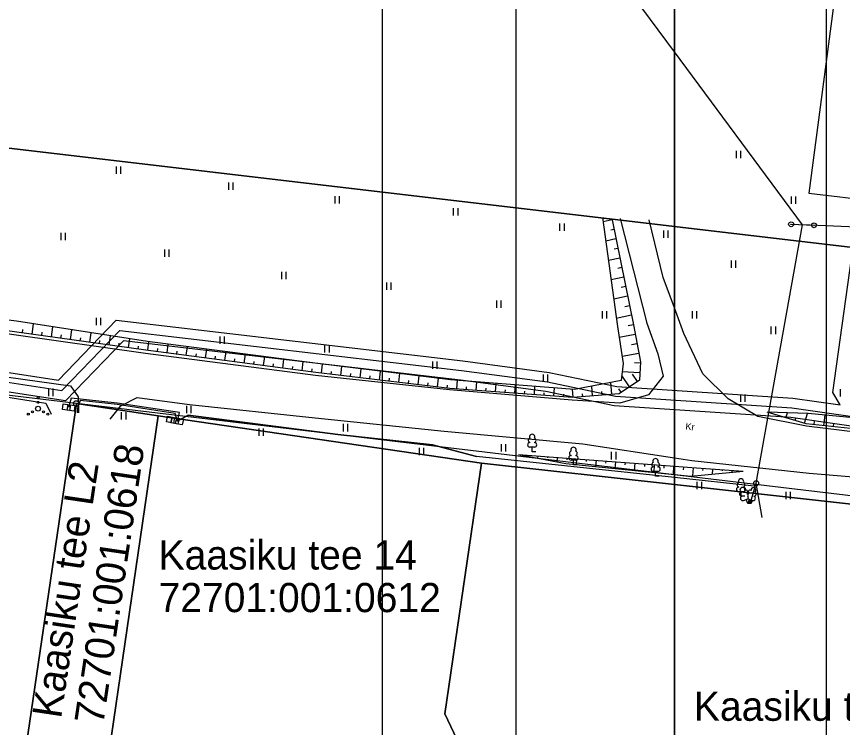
# Model space of a CAD drawing. Extents: x 532656 to 533339, y 6581345 to 6581629.
# Drawn here: x 532930.1 to 533015, y 6581458.9 to 6581531.9 of the extents above; entities that cross this region are included whole.
import ezdxf

# ---------------------------------------------------------------- set-up
doc = ezdxf.new("R2010")
doc.units = 0
for name, color, linetype in [('ELRAJATISMP', 7, 'Continuous'), ('HALJASTUS', 7, 'Continuous'), ('KASUTUSALA', 7, 'Continuous'), ('MPKAABEL', 7, 'Continuous'), ('MPOHULIIN', 7, 'Continuous'), ('PIIR', 7, 'Continuous'), ('PIIRIMLEITUD', 7, 'Continuous'), ('POST', 7, 'Continuous'), ('PR_SIDE', 7, 'Continuous'), ('PUU', 7, 'Continuous'), ('RAJATIS', 7, 'Continuous'), ('RELJEEF', 7, 'Continuous'), ('TEE', 7, 'Continuous'), ('VORMISTUS', 7, 'Continuous'), ('VORMISTUS_1', 7, 'Continuous')]:
    doc.layers.add(name, color=color, linetype=linetype)

msp = doc.modelspace()

# ---------------------------------------------------------------- linework, layer by layer
at = {"layer": 'ELRAJATISMP'}
for p, q in [((532935.363, 6581492.081), (532935.278, 6581491.49)), ((532935.632, 6581492.042), (532935.546, 6581491.452)), ((532946.08, 6581490.776), (532945.961, 6581490.191)), ((532946.346, 6581490.722), (532946.227, 6581490.137)), ((532946.53, 6581490.696), (532946.415, 6581490.11)), ((532946.797, 6581490.643), (532946.681, 6581490.058))]:
    msp.add_line(p, q, dxfattribs=at)
for points in [[(532934.906, 6581492.147), (532936.088, 6581491.977), (532936.003, 6581491.386), (532934.821, 6581491.556)], [(532945.627, 6581490.868), (532946.798, 6581490.63), (532946.679, 6581490.046), (532945.509, 6581490.283)], [(532946.077, 6581490.785), (532947.249, 6581490.554), (532947.134, 6581489.969), (532945.962, 6581490.199)]]:
    msp.add_lwpolyline(points, close=True, dxfattribs=at)
at = {"layer": 'HALJASTUS'}
for p, q in [((533004.032, 6581518.145), (533004.032, 6581517.384)), ((533004.487, 6581518.145), (533004.487, 6581517.384)), ((532940.342, 6581516.519), (532940.342, 6581515.758)), ((532940.797, 6581516.519), (532940.797, 6581515.758)), ((532951.862, 6581514.893), (532951.862, 6581514.132)), ((532952.317, 6581514.893), (532952.317, 6581514.132)), ((532962.792, 6581513.489), (532962.792, 6581512.728)), ((532963.247, 6581513.489), (532963.247, 6581512.728)), ((533009.686, 6581513.457), (533009.686, 6581512.696)), ((533010.141, 6581513.457), (533010.141, 6581512.696)), ((532974.977, 6581512.233), (532974.977, 6581511.472)), ((532975.432, 6581512.233), (532975.432, 6581511.472)), ((532985.907, 6581510.681), (532985.907, 6581509.92)), ((532986.362, 6581510.681), (532986.362, 6581509.92)), ((532934.652, 6581509.708), (532934.652, 6581508.947)), ((532935.107, 6581509.708), (532935.107, 6581508.947)), ((532996.562, 6581509.952), (532996.562, 6581509.191)), ((532997.017, 6581509.952), (532997.017, 6581509.191)), ((532945.287, 6581508.008), (532945.287, 6581507.247)), ((532945.742, 6581508.008), (532945.742, 6581507.247)), ((533003.525, 6581506.87), (533003.525, 6581506.109)), ((533003.98, 6581506.87), (533003.98, 6581506.109)), ((532957.324, 6581505.717), (532957.324, 6581504.956)), ((532957.779, 6581505.717), (532957.779, 6581504.956)), ((532968.106, 6581504.609), (532968.106, 6581503.848)), ((532968.561, 6581504.609), (532968.561, 6581503.848)), ((532979.405, 6581502.761), (532979.405, 6581502)), ((532979.86, 6581502.761), (532979.86, 6581502)), ((532990.261, 6581501.653), (532990.261, 6581500.892)), ((532990.716, 6581501.653), (532990.716, 6581500.892)), ((532999.516, 6581501.676), (532999.516, 6581500.914)), ((532999.971, 6581501.676), (532999.971, 6581500.914)), ((532938.271, 6581500.988), (532938.271, 6581500.227)), ((532938.726, 6581500.988), (532938.726, 6581500.227)), ((533007.618, 6581500.071), (533007.618, 6581499.31)), ((533008.074, 6581500.071), (533008.074, 6581499.31)), ((532950.973, 6581499.067), (532950.973, 6581498.305)), ((532951.428, 6581499.067), (532951.428, 6581498.305)), ((532961.755, 6581498.18), (532961.755, 6581497.419)), ((532962.21, 6581498.18), (532962.21, 6581497.419)), ((532972.832, 6581496.48), (532972.832, 6581495.719)), ((532973.287, 6581496.48), (532973.287, 6581495.719)), ((532984.205, 6581495.15), (532984.205, 6581494.389)), ((532984.66, 6581495.15), (532984.66, 6581494.389)), ((532933.385, 6581493.7), (532933.385, 6581492.939)), ((532933.84, 6581493.7), (532933.84, 6581492.939)), ((533014.75, 6581493.652), (533014.75, 6581492.891)), ((533004.496, 6581493.103), (533004.496, 6581492.342)), ((533004.951, 6581493.103), (533004.951, 6581492.342)), ((532947.564, 6581491.926), (532947.564, 6581491.165)), ((532948.019, 6581491.926), (532948.019, 6581491.165)), ((532940.86, 6581491.299), (532940.86, 6581490.538)), ((532941.315, 6581491.299), (532941.315, 6581490.538)), ((532954.997, 6581489.604), (532954.997, 6581488.842)), ((532955.452, 6581489.604), (532955.452, 6581488.842)), ((532963.648, 6581490.068), (532963.648, 6581489.307)), ((532964.103, 6581490.068), (532964.103, 6581489.307)), ((532979.901, 6581487.993), (532979.901, 6581487.232)), ((532980.356, 6581487.993), (532980.356, 6581487.232)), ((532971.455, 6581487.619), (532971.455, 6581486.858)), ((532971.91, 6581487.619), (532971.91, 6581486.858)), ((532991.21, 6581487.191), (532991.21, 6581486.429)), ((532991.665, 6581487.191), (532991.665, 6581486.429)), ((533000.018, 6581484.132), (533000.018, 6581483.371)), ((533000.473, 6581484.132), (533000.473, 6581483.371)), ((533009.133, 6581483.1), (533009.133, 6581482.339)), ((533009.588, 6581483.1), (533009.588, 6581482.339))]:
    msp.add_line(p, q, dxfattribs=at)
msp.add_lwpolyline([(532892.02, 6581496.19), (532895.502, 6581498.379), (532904.073, 6581497.349), (532916.051, 6581494.964), (532928.105, 6581493.009), (532933.125, 6581492.214), (532933.659, 6581491.084)], dxfattribs=at)
for centre, radius in [((532932.31, 6581492.791), 0.1), ((532932.31, 6581491.641), 0.25), ((532932.31, 6581492.291), 0.1), ((532931.31, 6581491.066), 0.1), ((532931.745, 6581491.316), 0.1), ((532932.875, 6581491.316), 0.1), ((532933.31, 6581491.066), 0.1)]:
    msp.add_circle(centre, radius, dxfattribs=at)
at = {"layer": 'KASUTUSALA'}
for points in [[(532799.662, 6581479.424), (532838.202, 6581500.971), (532843.839, 6581502.808), (532856.06, 6581504.74), (532864.381, 6581504.708), (532878.783, 6581502.228), (532905.462, 6581499.009), (532934.405, 6581494.582), (532940.328, 6581500.726), (532975.953, 6581496.54), (532984.828, 6581495.375), (532991.779, 6581493.915), (533009.862, 6581492.726), (533014.729, 6581492.033), (533013.98, 6581493.304), (533015.896, 6581507.087)], [(533020.132, 6581489.243), (533009.655, 6581490.735), (532991.507, 6581491.928), (532984.492, 6581493.402), (532975.706, 6581494.555), (532941.079, 6581498.624), (532935.126, 6581492.449), (532905.191, 6581497.027), (532878.493, 6581500.248), (532864.206, 6581502.709), (532856.214, 6581502.739), (532844.308, 6581500.857), (532839.008, 6581499.129), (532800.682, 6581477.703)]]:
    msp.add_lwpolyline(points, dxfattribs=at)
at = {"layer": 'MPKAABEL'}
for p, q in [((532997.696, 6581484.555), (532977.35, 6581486.727)), ((533005.909, 6581483.678), (532997.696, 6581484.555))]:
    msp.add_line(p, q, dxfattribs=at)
for points in [[(532946.644, 6581490.354), (532946.827, 6581491.247), (532940.446, 6581492.21), (532935.695, 6581492.724), (532935.431, 6581491.762)], [(532946.644, 6581490.354), (532946.827, 6581491.247), (532940.446, 6581492.21), (532935.695, 6581492.724), (532935.431, 6581491.762)], [(532946.644, 6581490.354), (532946.385, 6581491.162), (532940.427, 6581492.061), (532936.642, 6581492.471), (532936.375, 6581491.643), (532936.311, 6581491.217)], [(532946.644, 6581490.354), (532946.385, 6581491.162), (532940.427, 6581492.061), (532936.642, 6581492.471), (532936.375, 6581491.643), (532936.311, 6581491.217)], [(532997.696, 6581484.555), (532977.35, 6581486.727), (532972.847, 6581487.936), (532963.128, 6581488.985), (532947.726, 6581490.986), (532946.644, 6581490.354)], [(532946.644, 6581490.354), (532947.726, 6581490.986), (532963.128, 6581488.985), (532972.847, 6581487.936), (532977.35, 6581486.727)], [(533006.107, 6581483.987), (533005.909, 6581483.678), (532997.696, 6581484.555)]]:
    msp.add_lwpolyline(points, dxfattribs=at)
at = {"layer": 'MPOHULIIN'}
msp.add_line((532997.696, 6581528.314), (532981.493, 6581550.179), dxfattribs=at)
for points in [[(533275.324, 6581502.368), (533268.528, 6581499.278), (533228.294, 6581500.866), (533187.877, 6581502.842), (533141.428, 6581504.881), (533095.447, 6581506.847), (533050.545, 6581508.805), (533010.87, 6581510.537), (532997.696, 6581528.314)], [(533006.722, 6581480.474), (533006.107, 6581483.987), (533010.87, 6581510.537)]]:
    msp.add_lwpolyline(points, dxfattribs=at)
at = {"layer": 'PIIR'}
for points in [[(532997.696, 6581510.35), (532853.02, 6581527.38), (532766.54, 6581476.67), (532710.965, 6581584.147)], [(532997.696, 6581558.346), (533016.96, 6581555.16), (533011.51, 6581513.79), (533060.19, 6581508.02), (533066.33, 6581546.98), (533091.13, 6581542.87), (533143.65, 6581562.67), (533173.8, 6581529.09), (533205.25, 6581513.98), (533125.12, 6581495.35), (532997.696, 6581510.35)], [(532997.696, 6581510.35), (533125.12, 6581495.35), (533271.76, 6581529.44), (533289.68, 6581507.68), (533127.07, 6581468.59), (533126.77, 6581469.47), (532997.696, 6581484.842)], [(532997.696, 6581484.842), (532936.25, 6581492.16), (532895.36, 6581497.07), (532858.61, 6581500.62), (532765.26, 6581446.64), (532740.99, 6581450.83), (532726.7, 6581453.3), (532853.02, 6581527.38), (532997.696, 6581510.35)], [(532997.696, 6581484.842), (532936.25, 6581492.16), (532944.64, 6581490.92), (532977.88, 6581486.06), (532997.696, 6581483.863)], [(532997.696, 6581483.863), (532977.88, 6581486.06), (532974.12, 6581460.29), (532983.42, 6581440.62), (532985.67, 6581435.87), (532997.696, 6581433.84)], [(532997.696, 6581483.863), (533035.33, 6581479.69), (533123.26, 6581468.15), (533127.07, 6581468.59), (533126.77, 6581469.47), (532997.696, 6581484.842)], [(532997.696, 6581433.84), (533019.26, 6581430.2), (533032.98, 6581458.23), (533035.33, 6581479.69), (532997.696, 6581483.863)]]:
    msp.add_lwpolyline(points, dxfattribs=at)
for points in [[(533066.33, 6581546.98), (533016.96, 6581555.16), (533011.51, 6581513.79), (533060.19, 6581508.02)], [(532895.36, 6581497.07), (532888.42, 6581457.95), (532930.2, 6581450.9), (532936.25, 6581492.16)], [(532936.25, 6581492.16), (532930.2, 6581450.9), (532937.97, 6581439.75), (532947.82, 6581446.61), (532939.84, 6581458.06), (532944.64, 6581490.92)], [(532944.64, 6581490.92), (532939.84, 6581458.06), (532947.82, 6581446.61), (532983.42, 6581440.62), (532974.12, 6581460.29), (532977.88, 6581486.06)]]:
    msp.add_lwpolyline(points, close=True, dxfattribs=at)
at = {"layer": 'PIIRIMLEITUD'}
msp.add_circle((532936.233, 6581492.169), 0.285, dxfattribs=at)
at = {"layer": 'POST'}
msp.add_lwpolyline([(533005.546, 6581482.101), (533006.107, 6581483.987)], dxfattribs=at)
for centre, radius in [((533009.691, 6581510.589), 0.25), ((533009.691, 6581510.589), 0.0234), ((533012.048, 6581510.486), 0.25), ((533012.048, 6581510.486), 0.0234), ((533006.107, 6581483.987), 0.25), ((533005.546, 6581482.101), 0.125), ((533005.546, 6581482.101), 0.105), ((533005.546, 6581482.101), 0.0851), ((533005.546, 6581482.101), 0.0651), ((533005.546, 6581482.101), 0.0451), ((533005.546, 6581482.101), 0.0251), ((533005.546, 6581482.101), 0.00511)]:
    msp.add_circle(centre, radius, dxfattribs=at)
at = {"layer": 'PR_SIDE'}
msp.add_lwpolyline([(532685.797, 6581460.812), (532752.673, 6581449.895), (532752.642, 6581449.863), (532756.241, 6581452.319), (532771.22, 6581460.368), (532800.172, 6581478.564), (532838.605, 6581500.05), (532844.074, 6581501.833), (532856.137, 6581503.74), (532864.294, 6581503.709), (532878.638, 6581501.239), (532905.327, 6581498.018), (532934.766, 6581493.516), (532940.704, 6581499.675), (532975.83, 6581495.548), (532984.66, 6581494.389), (532991.644, 6581492.922), (533009.759, 6581491.731), (533020.322, 6581490.227)], dxfattribs=at)
at = {"layer": 'PUU'}
for p, q in [((532983.32, 6581487.693), (532982.84, 6581487.693)), ((532983.08, 6581487.218), (532983.08, 6581487.693)), ((532983.46, 6581487.218), (532983.08, 6581487.218)), ((532987.559, 6581486.356), (532987.079, 6581486.356)), ((532987.319, 6581485.881), (532987.319, 6581486.356)), ((532987.699, 6581485.881), (532987.319, 6581485.881)), ((532996.01, 6581485.187), (532995.53, 6581485.187)), ((532995.77, 6581484.712), (532995.77, 6581485.187)), ((532996.15, 6581484.712), (532995.77, 6581484.712)), ((533004.785, 6581483.113), (533004.306, 6581483.113)), ((533004.545, 6581482.638), (533004.545, 6581483.113)), ((533004.926, 6581482.638), (533004.545, 6581482.638)), ((533004.81, 6581482.218), (533005.255, 6581482.393)), ((533005.25, 6581481.883), (533005.075, 6581482.323)), ((533005.25, 6581481.883), (533005.43, 6581482.323)), ((533005.63, 6581481.883), (533005.25, 6581481.883)), ((533005.255, 6581482.393), (533005.695, 6581482.213))]:
    msp.add_line(p, q, dxfattribs=at)
msp.add_lwpolyline([(533005.255, 6581482.888), (533005.235, 6581482.813), (533005.235, 6581482.793), (533005.245, 6581482.763), (533005.265, 6581482.728), (533005.27, 6581482.708), (533005.255, 6581482.673), (533005.23, 6581482.623), (533005.225, 6581482.598), (533005.23, 6581482.583), (533005.24, 6581482.553), (533005.275, 6581482.493), (533005.28, 6581482.473), (533005.275, 6581482.453), (533005.26, 6581482.418), (533005.255, 6581482.393)], dxfattribs=at)
for centre, radius, start, end in [((532982.91, 6581488.39), 0.233, 109.02174, 253.14154), ((532983.08, 6581488.738), 0.277, 332.5799, 207.4201), ((532983.25, 6581488.39), 0.233, 286.85082, 70.98591), ((532982.842, 6581487.93), 0.238, 90.0016, 269.3953), ((532983.317, 6581487.93), 0.238, 270.6047, 89.9984), ((532987.319, 6581487.401), 0.277, 332.5799, 207.4201), ((532987.081, 6581486.594), 0.238, 90.0016, 269.3953), ((532987.148, 6581487.054), 0.233, 109.02174, 253.14154), ((532987.489, 6581487.054), 0.233, 286.85082, 70.98591), ((532987.556, 6581486.594), 0.238, 270.6047, 89.9984), ((532995.6, 6581485.884), 0.233, 109.02174, 253.14154), ((532995.77, 6581486.232), 0.277, 332.5799, 207.4201), ((532995.94, 6581485.884), 0.233, 286.85082, 70.98591), ((532995.533, 6581485.424), 0.238, 90.0016, 269.3953), ((532996.008, 6581485.424), 0.238, 270.6047, 89.9984), ((533004.545, 6581484.158), 0.277, 332.5799, 207.4201), ((533004.308, 6581483.351), 0.238, 90.0016, 269.3953), ((533004.375, 6581483.811), 0.233, 109.02174, 253.14154), ((533004.693, 6581483.297), 0.256, 111.50269, 232.51731), ((533004.693, 6581483.297), 0.256, 350.48556, 111.50017), ((533004.716, 6581483.811), 0.233, 286.85082, 70.98591), ((533004.783, 6581483.351), 0.238, 270.6047, 89.9984), ((533005.829, 6581483.289), 0.256, 67.6168, 188.63142), ((533005.829, 6581483.289), 0.256, 306.59966, 67.61428), ((533004.619, 6581482.886), 0.224, 111.43041, 274.49868), ((533004.724, 6581482.442), 0.237, 111.50143, 291.50036), ((533005.028, 6581483.047), 0.224, 308.50412, 111.57247), ((533005.254, 6581482.65), 0.237, 66.76552, 111.50149), ((533005.491, 6581483.042), 0.225, 67.7016, 230.51262), ((533005.785, 6581482.433), 0.237, 247.61661, 67.61554), ((533005.897, 6581482.876), 0.224, 264.6183, 67.68657)]:
    msp.add_arc(centre, radius, start, end, dxfattribs=at)
at = {"layer": 'RAJATIS'}
msp.add_line((533009.691, 6581510.589), (533012.048, 6581510.486), dxfattribs=at)
at = {"layer": 'RELJEEF'}
for p, q in [((532991.295, 6581511.036), (532990.379, 6581510.849)), ((532991.494, 6581510.056), (532991.167, 6581509.989)), ((532991.694, 6581509.076), (532990.649, 6581508.863)), ((532991.894, 6581508.096), (532991.524, 6581508.021)), ((532992.093, 6581507.116), (532990.919, 6581506.877)), ((532992.293, 6581506.136), (532991.88, 6581506.052)), ((532992.493, 6581505.157), (532991.189, 6581504.891)), ((532992.692, 6581504.177), (532992.236, 6581504.084)), ((532992.892, 6581503.197), (532991.46, 6581502.905)), ((532993.092, 6581502.217), (532992.593, 6581502.115)), ((532993.291, 6581501.237), (532991.73, 6581500.919)), ((532930.704, 6581499.429), (532930.754, 6581499.789)), ((532931.694, 6581499.291), (532931.842, 6581500.356)), ((532933.675, 6581499.016), (532933.819, 6581500.051)), ((532935.656, 6581498.741), (532935.796, 6581499.746)), ((532993.491, 6581500.257), (532992.95, 6581500.147)), ((532932.685, 6581499.153), (532932.733, 6581499.504)), ((532934.666, 6581498.878), (532934.713, 6581499.218)), ((532936.647, 6581498.603), (532936.692, 6581498.933)), ((532937.637, 6581498.465), (532937.772, 6581499.44)), ((532939.618, 6581498.19), (532939.749, 6581499.135)), ((532941.599, 6581497.915), (532941.726, 6581498.83)), ((532993.675, 6581499.274), (532992.018, 6581498.964)), ((532938.628, 6581498.328), (532938.672, 6581498.648)), ((532940.608, 6581498.053), (532940.652, 6581498.363)), ((532942.589, 6581497.777), (532942.631, 6581498.077)), ((532943.58, 6581497.641), (532943.698, 6581498.529)), ((532945.563, 6581497.378), (532945.681, 6581498.272)), ((532947.545, 6581497.116), (532947.665, 6581498.015)), ((532993.86, 6581498.292), (532993.297, 6581498.186)), ((532944.571, 6581497.51), (532944.611, 6581497.807)), ((532946.554, 6581497.247), (532946.594, 6581497.546)), ((532948.537, 6581496.984), (532948.577, 6581497.285)), ((532949.528, 6581496.853), (532949.648, 6581497.757)), ((532950.519, 6581496.722), (532950.56, 6581497.024)), ((532951.511, 6581496.59), (532951.631, 6581497.5)), ((532953.493, 6581496.327), (532953.615, 6581497.243)), ((532955.476, 6581496.065), (532955.598, 6581496.986)), ((532994.044, 6581497.309), (532992.326, 6581496.986)), ((532952.502, 6581496.459), (532952.542, 6581496.763)), ((532954.485, 6581496.196), (532954.525, 6581496.502)), ((532956.467, 6581495.933), (532956.508, 6581496.242)), ((532957.459, 6581495.802), (532957.582, 6581496.729)), ((532959.441, 6581495.539), (532959.565, 6581496.472)), ((532961.425, 6581495.285), (532961.535, 6581496.22)), ((532994.198, 6581496.324), (532993.603, 6581496.356)), ((532958.45, 6581495.671), (532958.491, 6581495.981)), ((532960.433, 6581495.408), (532960.474, 6581495.72)), ((532962.418, 6581495.168), (532962.455, 6581495.478)), ((532963.411, 6581495.051), (532963.521, 6581495.978)), ((532965.398, 6581494.816), (532965.506, 6581495.735)), ((532967.384, 6581494.582), (532967.491, 6581495.492)), ((532994.143, 6581495.325), (532992.338, 6581495.423)), ((532964.405, 6581494.933), (532964.441, 6581495.241)), ((532966.391, 6581494.699), (532966.427, 6581495.004)), ((532968.377, 6581494.465), (532968.413, 6581494.767)), ((532969.37, 6581494.348), (532969.476, 6581495.249)), ((532970.363, 6581494.231), (532970.398, 6581494.53)), ((532971.356, 6581494.114), (532971.462, 6581495.006)), ((532973.343, 6581493.88), (532973.447, 6581494.763)), ((532975.332, 6581493.676), (532975.398, 6581494.555)), ((532993.069, 6581493.88), (532992.296, 6581495.039)), ((532993.901, 6581494.434), (532993.389, 6581495.203)), ((532972.35, 6581493.997), (532972.384, 6581494.293)), ((532974.336, 6581493.763), (532974.37, 6581494.056)), ((532976.329, 6581493.601), (532976.351, 6581493.893)), ((532977.326, 6581493.526), (532977.392, 6581494.399)), ((532978.323, 6581493.45), (532978.345, 6581493.741)), ((532979.32, 6581493.375), (532979.386, 6581494.243)), ((532980.318, 6581493.3), (532980.339, 6581493.588)), ((532981.315, 6581493.225), (532981.38, 6581494.087)), ((532983.309, 6581493.075), (532983.374, 6581493.931)), ((532985.304, 6581492.924), (532985.368, 6581493.775)), ((532987.298, 6581492.781), (532987.226, 6581493.629)), ((532989.291, 6581492.949), (532989.206, 6581493.957)), ((532991.284, 6581493.117), (532991.18, 6581494.342)), ((532992.237, 6581493.325), (532991.996, 6581493.686)), ((532982.312, 6581493.15), (532982.334, 6581493.436)), ((532984.306, 6581492.999), (532984.328, 6581493.284)), ((532986.301, 6581492.849), (532986.322, 6581493.131)), ((532988.294, 6581492.865), (532988.269, 6581493.165)), ((532990.287, 6581493.033), (532990.256, 6581493.405)), ((533007.243, 6581491.268), (533007.244, 6581491.27)), ((533008.203, 6581490.987), (533008.227, 6581491.07)), ((533009.162, 6581490.705), (533009.308, 6581491.201)), ((533011.081, 6581490.141), (533011.372, 6581491.131)), ((533010.122, 6581490.423), (533010.194, 6581490.671)), ((533012.069, 6581490.005), (533012.106, 6581490.356)), ((533013.064, 6581489.899), (533013.177, 6581490.967)), ((533014.058, 6581489.794), (533014.096, 6581490.154)), ((532982.665, 6581486.847), (532982.663, 6581486.81)), ((532983.663, 6581486.777), (532983.647, 6581486.554)), ((532984.66, 6581486.707), (532984.652, 6581486.595)), ((532985.658, 6581486.637), (532985.626, 6581486.191)), ((532986.655, 6581486.567), (532986.642, 6581486.383)), ((532987.652, 6581486.49), (532987.608, 6581485.913)), ((532988.649, 6581486.414), (532988.634, 6581486.213)), ((532989.647, 6581486.337), (532989.599, 6581485.711)), ((532990.644, 6581486.261), (532990.627, 6581486.044)), ((532991.641, 6581486.185), (532991.589, 6581485.509)), ((532992.638, 6581486.108), (532992.62, 6581485.875)), ((532993.635, 6581486.032), (532993.579, 6581485.307)), ((532994.632, 6581485.955), (532994.613, 6581485.705)), ((532995.629, 6581485.879), (532995.57, 6581485.104)), ((532996.626, 6581485.802), (532996.606, 6581485.536)), ((532997.623, 6581485.726), (532997.56, 6581484.902)), ((532998.62, 6581485.649), (532998.598, 6581485.367)), ((532999.617, 6581485.574), (532999.561, 6581484.733)), ((533000.615, 6581485.507), (533000.6, 6581485.281)), ((533001.613, 6581485.441), (533001.579, 6581484.926)), ((533002.611, 6581485.374), (533002.603, 6581485.257)), ((533003.608, 6581485.308), (533003.596, 6581485.119)), ((533004.606, 6581485.241), (533004.606, 6581485.233))]:
    msp.add_line(p, q, dxfattribs=at)
for points in [[(532990.32, 6581511.282), (532991.842, 6581500.091), (532992.434, 6581496.294), (532992.243, 6581494.55), (532987.443, 6581493.612), (532974.703, 6581494.609), (532961.03, 6581496.282), (532943.56, 6581498.546), (532930.091, 6581500.627), (532917.608, 6581502.219), (532904.555, 6581504.35), (532889.827, 6581506.424), (532874.089, 6581508.532), (532860.585, 6581510.222), (532852.458, 6581510.268)], [(532991.295, 6581511.036), (532993.491, 6581500.256), (532994.205, 6581496.453), (532994.102, 6581494.569), (532992.018, 6581493.179), (532987.251, 6581492.777), (532974.607, 6581493.731), (532960.859, 6581495.351), (532943.377, 6581497.668), (532929.887, 6581499.542), (532917.361, 6581501.265), (532904.238, 6581503.289), (532889.482, 6581505.445), (532873.903, 6581507.739), (532860.397, 6581509.287), (532852.458, 6581510.268)], [(533029.716, 6581491.454), (533028.353, 6581489.429), (533026.644, 6581488.57), (533022.292, 6581488.923), (533011.253, 6581490.091), (533007.237, 6581491.27)], [(533029.716, 6581491.454), (533028.124, 6581490.032), (533026.747, 6581489.222), (533022.553, 6581490.095), (533011.436, 6581491.129), (533007.237, 6581491.27)], [(532981.668, 6581486.917), (532986.662, 6581486.566), (532997.696, 6581485.72)], [(532981.668, 6581486.917), (532986.553, 6581486.021), (532997.696, 6581484.888)], [(532997.696, 6581485.72), (532999.489, 6581485.583), (533004.763, 6581485.231)], [(532997.696, 6581484.888), (532999.389, 6581484.716), (533004.763, 6581485.231)]]:
    msp.add_lwpolyline(points, dxfattribs=at)
at = {"layer": 'TEE'}
for points in [[(532992.127, 6581511.166), (532994.877, 6581500.414), (532995.992, 6581497.284), (532996.535, 6581494.967), (532995.038, 6581493.06), (532992.109, 6581492.211), (532987.192, 6581492.522), (532974.603, 6581493.571), (532960.836, 6581495.043), (532943.355, 6581497.307), (532929.83, 6581499.24), (532917.328, 6581501.087), (532904.202, 6581503.175), (532889.432, 6581505.339), (532873.836, 6581507.526), (532860.39, 6581509.056), (532853.923, 6581509.639), (532847.694, 6581509.868), (532843.333, 6581510.842), (532837.551, 6581513.019), (532831.36, 6581515.277)], [(532997.696, 6581502.001), (532996.542, 6581505.112), (532995.097, 6581511.042)], [(533032.431, 6581507.077), (533031.38, 6581500.28), (533030.417, 6581493.077), (533030.024, 6581491.203), (533028.429, 6581489.235), (533026.625, 6581488.098), (533022.181, 6581488.518), (533011.268, 6581489.842), (533006.271, 6581490.826), (533003.238, 6581492.661), (533000.616, 6581495.226), (532998.671, 6581499.374), (532997.696, 6581502.001)], [(532889.672, 6581496.482), (532890.651, 6581498.163), (532892.641, 6581499.514), (532895.155, 6581500.05), (532903.662, 6581499.012), (532916.349, 6581496.974), (532929.017, 6581494.897), (532935.648, 6581493.994), (532936.42, 6581492.855), (532936.468, 6581491.225)], [(532939.733, 6581490.57), (532940.828, 6581491.946), (532942.508, 6581492.777), (532947.888, 6581492.067), (532960.794, 6581490.691), (532974.024, 6581489.347), (532988.298, 6581488.041), (532997.696, 6581486.593)], [(532997.696, 6581486.593), (532999.496, 6581486.316), (533011.555, 6581485.02), (533021.866, 6581484.146)]]:
    msp.add_lwpolyline(points, dxfattribs=at)
at = {"layer": 'VORMISTUS'}
for points in [[(532967.698, 6581629.013), (533338.948, 6581629.013), (533338.948, 6581366.513), (532967.698, 6581366.513)], [(532981.448, 6581379.013), (532981.448, 6581616.513), (533325.198, 6581616.513), (533325.198, 6581379.013)], [(532981.448, 6581616.513), (533325.198, 6581616.513), (533325.198, 6581379.013), (532981.448, 6581379.013)], [(533309.595, 6581421.679), (533309.595, 6581605.423), (532997.696, 6581605.423), (532997.696, 6581421.679)]]:
    msp.add_lwpolyline(points, close=True, dxfattribs=at)
msp.add_lwpolyline([(532997.696, 6581605.423), (532997.696, 6581421.679)], dxfattribs=at)
at = {"layer": 'VORMISTUS_1'}
for points in [[(532669.549, 6581357.737), (532669.549, 6581595.237), (533013.299, 6581595.237), (533013.299, 6581357.737)], [(532669.549, 6581595.237), (533013.299, 6581595.237), (533013.299, 6581357.737), (532669.549, 6581357.737)], [(532997.696, 6581400.404), (532997.696, 6581584.147), (532685.797, 6581584.147), (532685.797, 6581400.404)]]:
    msp.add_lwpolyline(points, close=True, dxfattribs=at)
msp.add_lwpolyline([(532997.696, 6581400.404), (532997.696, 6581584.147)], dxfattribs=at)

# ---------------------------------------------------------------- texts
at = {"layer": 'PIIR'}
for s, p in [('72701:001:0618', (532938.996, 6581459.091)), ('Kaasiku tee L2', (532934.668, 6581459.733))]:
    msp.add_text(s, height=3, rotation=81.56748, dxfattribs=at).set_placement(p)
for s, p in [('Kaasiku tee 14', (532944.695, 6581475.113)), ('72701:001:0612', (532944.695, 6581470.738)), ('Kaasiku tee 12', (532999.704, 6581459.575))]:
    msp.add_text(s, height=3, dxfattribs=at).set_placement(p)
at = {"layer": 'TEE'}
msp.add_text('Kr', height=0.7, rotation=353.26999, dxfattribs=at).set_placement((532998.801, 6581489.506))

doc.saveas('drawing.dxf')
